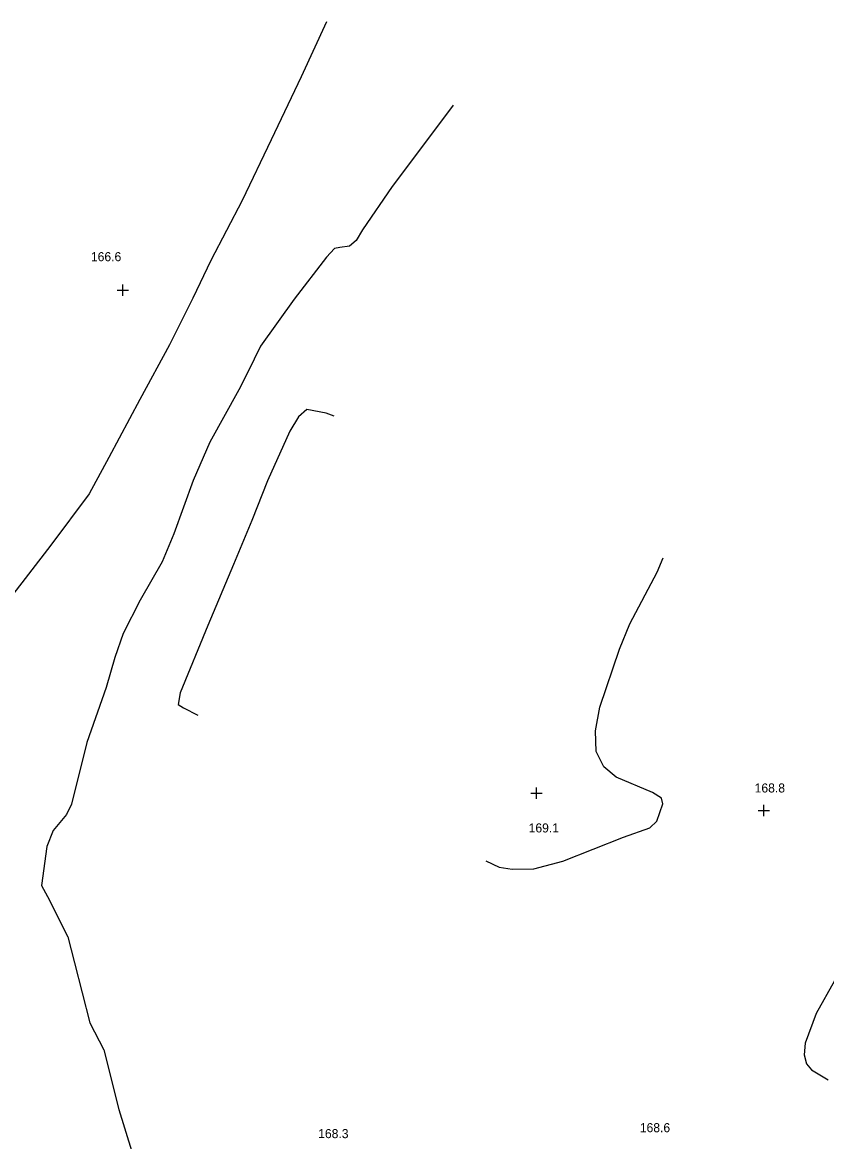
# Model space of a CAD drawing. Extents: x 1467615 to 2003689, y 770235 to 1108726.
# Drawn here: x 1998536.3 to 1998713.9, y 775726.9 to 775974.1 of the extents above; entities that cross this region are included whole.
import ezdxf

# ---------------------------------------------------------------- set-up
doc = ezdxf.new("R2010")
doc.units = 0
doc.layers.add('RD_DTM_Minor1', color=7, linetype='Continuous')
doc.layers.add('RD_DTM_Spot_Elev', color=7, linetype='Continuous')

msp = doc.modelspace()

# ---------------------------------------------------------------- linework, layer by layer
at = {"layer": 'RD_DTM_Minor1'}
for points in [[(1998603.45, 775974.21), (1998597.89, 775962.07), (1998591.23, 775948.16), (1998584.81, 775934.8), (1998577.95, 775921.53), (1998573.92, 775913.22), (1998568.78, 775902.9), (1998562.23, 775890.78), (1998555.44, 775877.99), (1998551.05, 775870.01), (1998542.63, 775858.67), (1998533.51, 775846.79)], [(1998631.43, 775955.81), (1998631.05, 775955.31), (1998617.96, 775937.89), (1998611.4, 775928.29), (1998610.01, 775925.9), (1998608.56, 775924.65), (1998606.4, 775924.4), (1998605.25, 775924.17), (1998603.48, 775922.25), (1998596.31, 775912.99), (1998588.89, 775902.56), (1998586.09, 775896.82), (1998584.09, 775892.95), (1998577.69, 775881.38), (1998574.02, 775872.93), (1998569.78, 775861.16), (1998567.19, 775854.98), (1998562.32, 775846.48), (1998558.6, 775839.15), (1998556.77, 775833.84), (1998554.85, 775827.21), (1998550.55, 775815.02), (1998547.2, 775801.42), (1998546.05, 775799.14), (1998543.16, 775795.64), (1998541.69, 775792.09), (1998540.55, 775783.49), (1998541.88, 775781.02), (1998546.38, 775772.13), (1998547.83, 775766.36), (1998551.2, 775753.11), (1998554.34, 775747.18), (1998557.63, 775733.98), (1998560.4, 775724.93)], [(1998605.12, 775887.11), (1998603.4, 775887.81), (1998599.09, 775888.57), (1998597.3, 775887), (1998595.37, 775883.79), (1998590.43, 775872.87), (1998586.97, 775864.08), (1998582.96, 775854.37), (1998577.26, 775840.88), (1998571.13, 775825.99), (1998570.71, 775823.43), (1998571.9, 775822.73), (1998575.04, 775821.09)], [(1998638.64, 775788.94), (1998641.6, 775787.53), (1998644.46, 775787.08), (1998649.2, 775787.16), (1998655.65, 775788.85), (1998669.03, 775794.17), (1998674.86, 775796.17), (1998676.42, 775797.69), (1998677.74, 775801.52), (1998677.44, 775802.74), (1998675.43, 775804.03), (1998667.4, 775807.37), (1998664.67, 775809.66), (1998662.99, 775813.03), (1998662.83, 775817.61), (1998663.82, 775822.85), (1998668.13, 775835.68), (1998670.46, 775841.26), (1998676.44, 775852.7), (1998677.77, 775855.86)], [(1998715.62, 775762.38), (1998711.57, 775755.22), (1998709.13, 775748.67), (1998708.89, 775746.07), (1998709.42, 775744.11), (1998710.51, 775742.72), (1998714.17, 775740.57)]]:
    msp.add_lwpolyline(points, dxfattribs=at)
at = {"layer": 'RD_DTM_Spot_Elev'}
for p, q in [((1998557.22, 775914.97), (1998559.72, 775914.97)), ((1998558.47, 775913.72), (1998558.47, 775916.22)), ((1998648.57, 775803.84), (1998651.07, 775803.84)), ((1998649.82, 775802.59), (1998649.82, 775805.09)), ((1998700, 775798.75), (1998700, 775801.25)), ((1998698.75, 775800), (1998701.25, 775800))]:
    msp.add_line(p, q, dxfattribs=at)

# ---------------------------------------------------------------- texts
for s, p in [('166.6', (1998551.46, 775921.36)), ('168.8', (1998697.98, 775804.01)), ('169.1', (1998648.09, 775795.18)), ('168.3', (1998601.63, 775727.66)), ('168.6', (1998672.63, 775728.97))]:
    msp.add_text(s, height=2, dxfattribs=at).set_placement(p)

doc.saveas('drawing.dxf')
